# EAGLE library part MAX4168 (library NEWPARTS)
High-Output-Drive, Precision, Low-power, Single-Supply, Rail-to-Rail I/O Op Amps with Shutdown
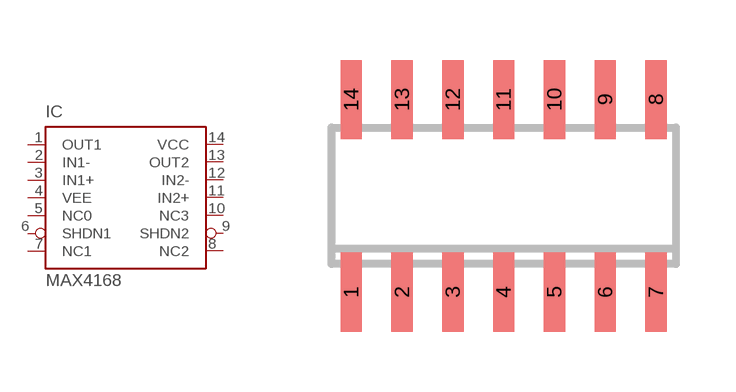
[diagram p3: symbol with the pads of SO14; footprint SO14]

Designator prefix IC

## MAX4168D  [SO14]
1  OUT1  pwr
2  IN1-  out
3  IN1+  in
4  VEE  in
5  NC0  in
6  SHDN1  in
7  NC1  in
8  NC2  pwr
9  SHDN2  pwr
10  NC3  out
11  IN2+  hiz
12  IN2-  in
13  OUT2  in
14  VCC  in

## Footprint SO14 (pad centres in mm)
Small Outline Package 14
smd 0.533 x 1.981: 1 -3.81,-2.219; 2 -2.54,-2.219; 3 -1.27,-2.219; 4 0,-2.219; 5 1.27,-2.219; 6 2.54,-2.219; 7 3.81,-2.219; 8 3.81,2.6; 9 2.54,2.6; 10 1.27,2.6; 11 0,2.6; 12 -1.27,2.6; 13 -2.54,2.6; 14 -3.81,2.6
